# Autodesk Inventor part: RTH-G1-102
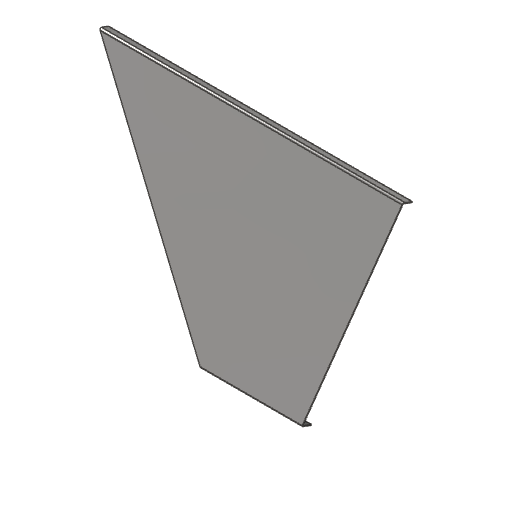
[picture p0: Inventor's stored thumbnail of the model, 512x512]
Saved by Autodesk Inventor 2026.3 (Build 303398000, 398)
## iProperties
Created: 2026-09
Part Number: RTH-G1-102
Material: Steel, Mild
Document SubType Name: Sheet Metal
Designer: mykol
Density: 7.85 g/cm^3
Sheet Metal Rule: Default_mm
Appearance: Semi-Polished
Project: RTH-G1
Description: PANEL Y+ 3 CS FORMED FLANGES
Stock Number: PL 3 x 1200 x 1040
Mass: 19425 g
Surface Area: 16611.6 cm^2
Volume: 2474.52 cm^3
Flat Pattern Width: 103.348 cm
Flat Pattern Length: 120 cm
Flat Pattern Area: 12401.8 cm^2
Sheet Metal Width: 1033.481 mm
Sheet Metal Length: 1200.000 mm
Sheet Metal Area: 1240177.359 mm^2
RuthenClass: Fabricated
Thickness: 3
RuthenConfigId: RTH-G1-A-b1a1fe2e
RuthenRuleSet: 1.0.0
RuthenAddInVersion: 1.0.0
Author: mykol
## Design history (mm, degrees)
node "Face1"
  sketch "Sketch1"
    geometry: L1 (-200, 0)-(200, 0); L2 (200, 0)-(600, 965.66); L3 (600, 965.66)-(-600, 965.66); L4 (-600, 965.66)-(-200, 0)
    constraints: 8 end point
node "Flange1"
node "Flange2"
body "Solid1"
face "Plate1" dims "d0" = 3 (= Thickness)
sketch "Sketch2"
  geometry: L1 through (600, 0) direction (-1, 0); L2 through (0, -20) direction (0, -1); L3 (0, -40)-(1200, -40); L4 (1200, -40)-(1200, 0)
  constraints: 6 end point, 1 horizontal, 1 perpendicular, 1 vertical
face "Plate2" dims "d0" = 3 (= Thickness), "d1" = 3 (= Thickness), "d2" = 1.5 (= 0.5 x Thickness), "d3" = 6 (= 2 x Thickness), "d4" = 3 (= Thickness), "d5" = 40, "d6" = 19.41688, "d7" = 3 (= Thickness), "d8" = 12 (= 4 x Thickness), "d9" = 0.5, "d10" = 3 (= JacobiRadiusSize), "SeamGap" = 0.01
bend "Bend1" dims "d0" = 3 (= Thickness), "d1" = 3 (= Thickness), "d2" = 1.5 (= 0.5 x Thickness), "d3" = 6 (= 2 x Thickness), "d4" = 3 (= Thickness), "d5" = 40, "d6" = 19.41688, "d7" = 3 (= Thickness), "SeamGap" = 0.01
feature "Corner1" dims "d5" = 40, "d6" = 19.41688, "d8" = 12 (= 4 x Thickness), "d9" = 0.5, "d10" = 3 (= JacobiRadiusSize)
sketch "Sketch3"
  geometry: L1 through (200, 0) direction (-1, 0); L2 through (0, -20) direction (0, -1); L3 (0, -40)-(400, -40); L4 (400, -40)-(400, 0)
  constraints: 6 end point, 1 horizontal, 1 perpendicular, 1 vertical
face "Plate3" dims "d0" = 3 (= Thickness), "d11" = 3 (= Thickness), "d12" = 1.5 (= 0.5 x Thickness), "d13" = 6 (= 2 x Thickness), "d14" = 3 (= Thickness), "d15" = 40, "d16" = 11.99905, "d17" = 3 (= Thickness), "d18" = 12 (= 4 x Thickness), "d19" = 0.5, "d20" = 3 (= JacobiRadiusSize), "SeamGap" = 0.01
bend "Bend2" dims "d0" = 3 (= Thickness), "d11" = 3 (= Thickness), "d12" = 1.5 (= 0.5 x Thickness), "d13" = 6 (= 2 x Thickness), "d14" = 3 (= Thickness), "d15" = 40, "d16" = 11.99905, "d17" = 3 (= Thickness), "SeamGap" = 0.01
feature "Corner2" dims "d15" = 40, "d16" = 11.99905, "d18" = 12 (= 4 x Thickness), "d19" = 0.5, "d20" = 3 (= JacobiRadiusSize)
feature "Definition1"
other parameters: "Thickness" = 3, "BendRadius" = 3 (= Thickness), "BendReliefWidth" = 3 (= Thickness), "BendReliefDepth" = 1.5 (= 0.5 x Thickness), "CornerReliefSize" = 12 (= 4 x Thickness), "MinimumRemnant" = 6 (= 2 x Thickness), "TransitionRadius" = 3 (= BendRadius), "JacobiRadiusSize" = 3 (= BendRadius), "GapSize" = 3 (= Thickness), "BendRadius" = 3, "BendReliefDepth" = 1.5, "BendReliefWidth" = 3, "CornerReliefSize" = 12, "GapSize" = 3, "JacobiRadiusSize" = 3, "MinimumRemnant" = 6, "Thickness" = 3, "TransitionRadius" = 3
